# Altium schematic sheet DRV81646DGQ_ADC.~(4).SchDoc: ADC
size 431 x 279 mm; Date: Not shown in title block; ApprovedBy: Not shown in title block; CheckedBy: Not shown in title block; Author: Not shown in title block; CompanyName: Not shown in title block; DrawnBy: Mojtaba Afshar; Engineer: Not shown in title block; Organization: Not shown in title block; Address1: Not shown in title block; Address2: Not shown in title block; Address3: Not shown in title block; Address4: Not shown in title block; DocumentNumber: 2; Revision: Use project parameter SCH_Rev; SheetNumber: 4; SheetTotal: 5; PageSetup: Record=PageOptions¦CenterHorizontal=True¦CenterVertical=True¦PrintScale=1.00¦XCorrection=1.00¦YCorrection=1.00¦PrintKind=0¦BorderSize=5000000¦LeftOffset=0¦BottomOffset=0¦Orientation=2¦PaperLength=1000¦PaperWidth=1000¦Scale=100¦PaperSource=15¦PrintQuality=600¦MediaType=1¦DitherType=10¦PaperKind=Letter¦PrintScaleMode=1
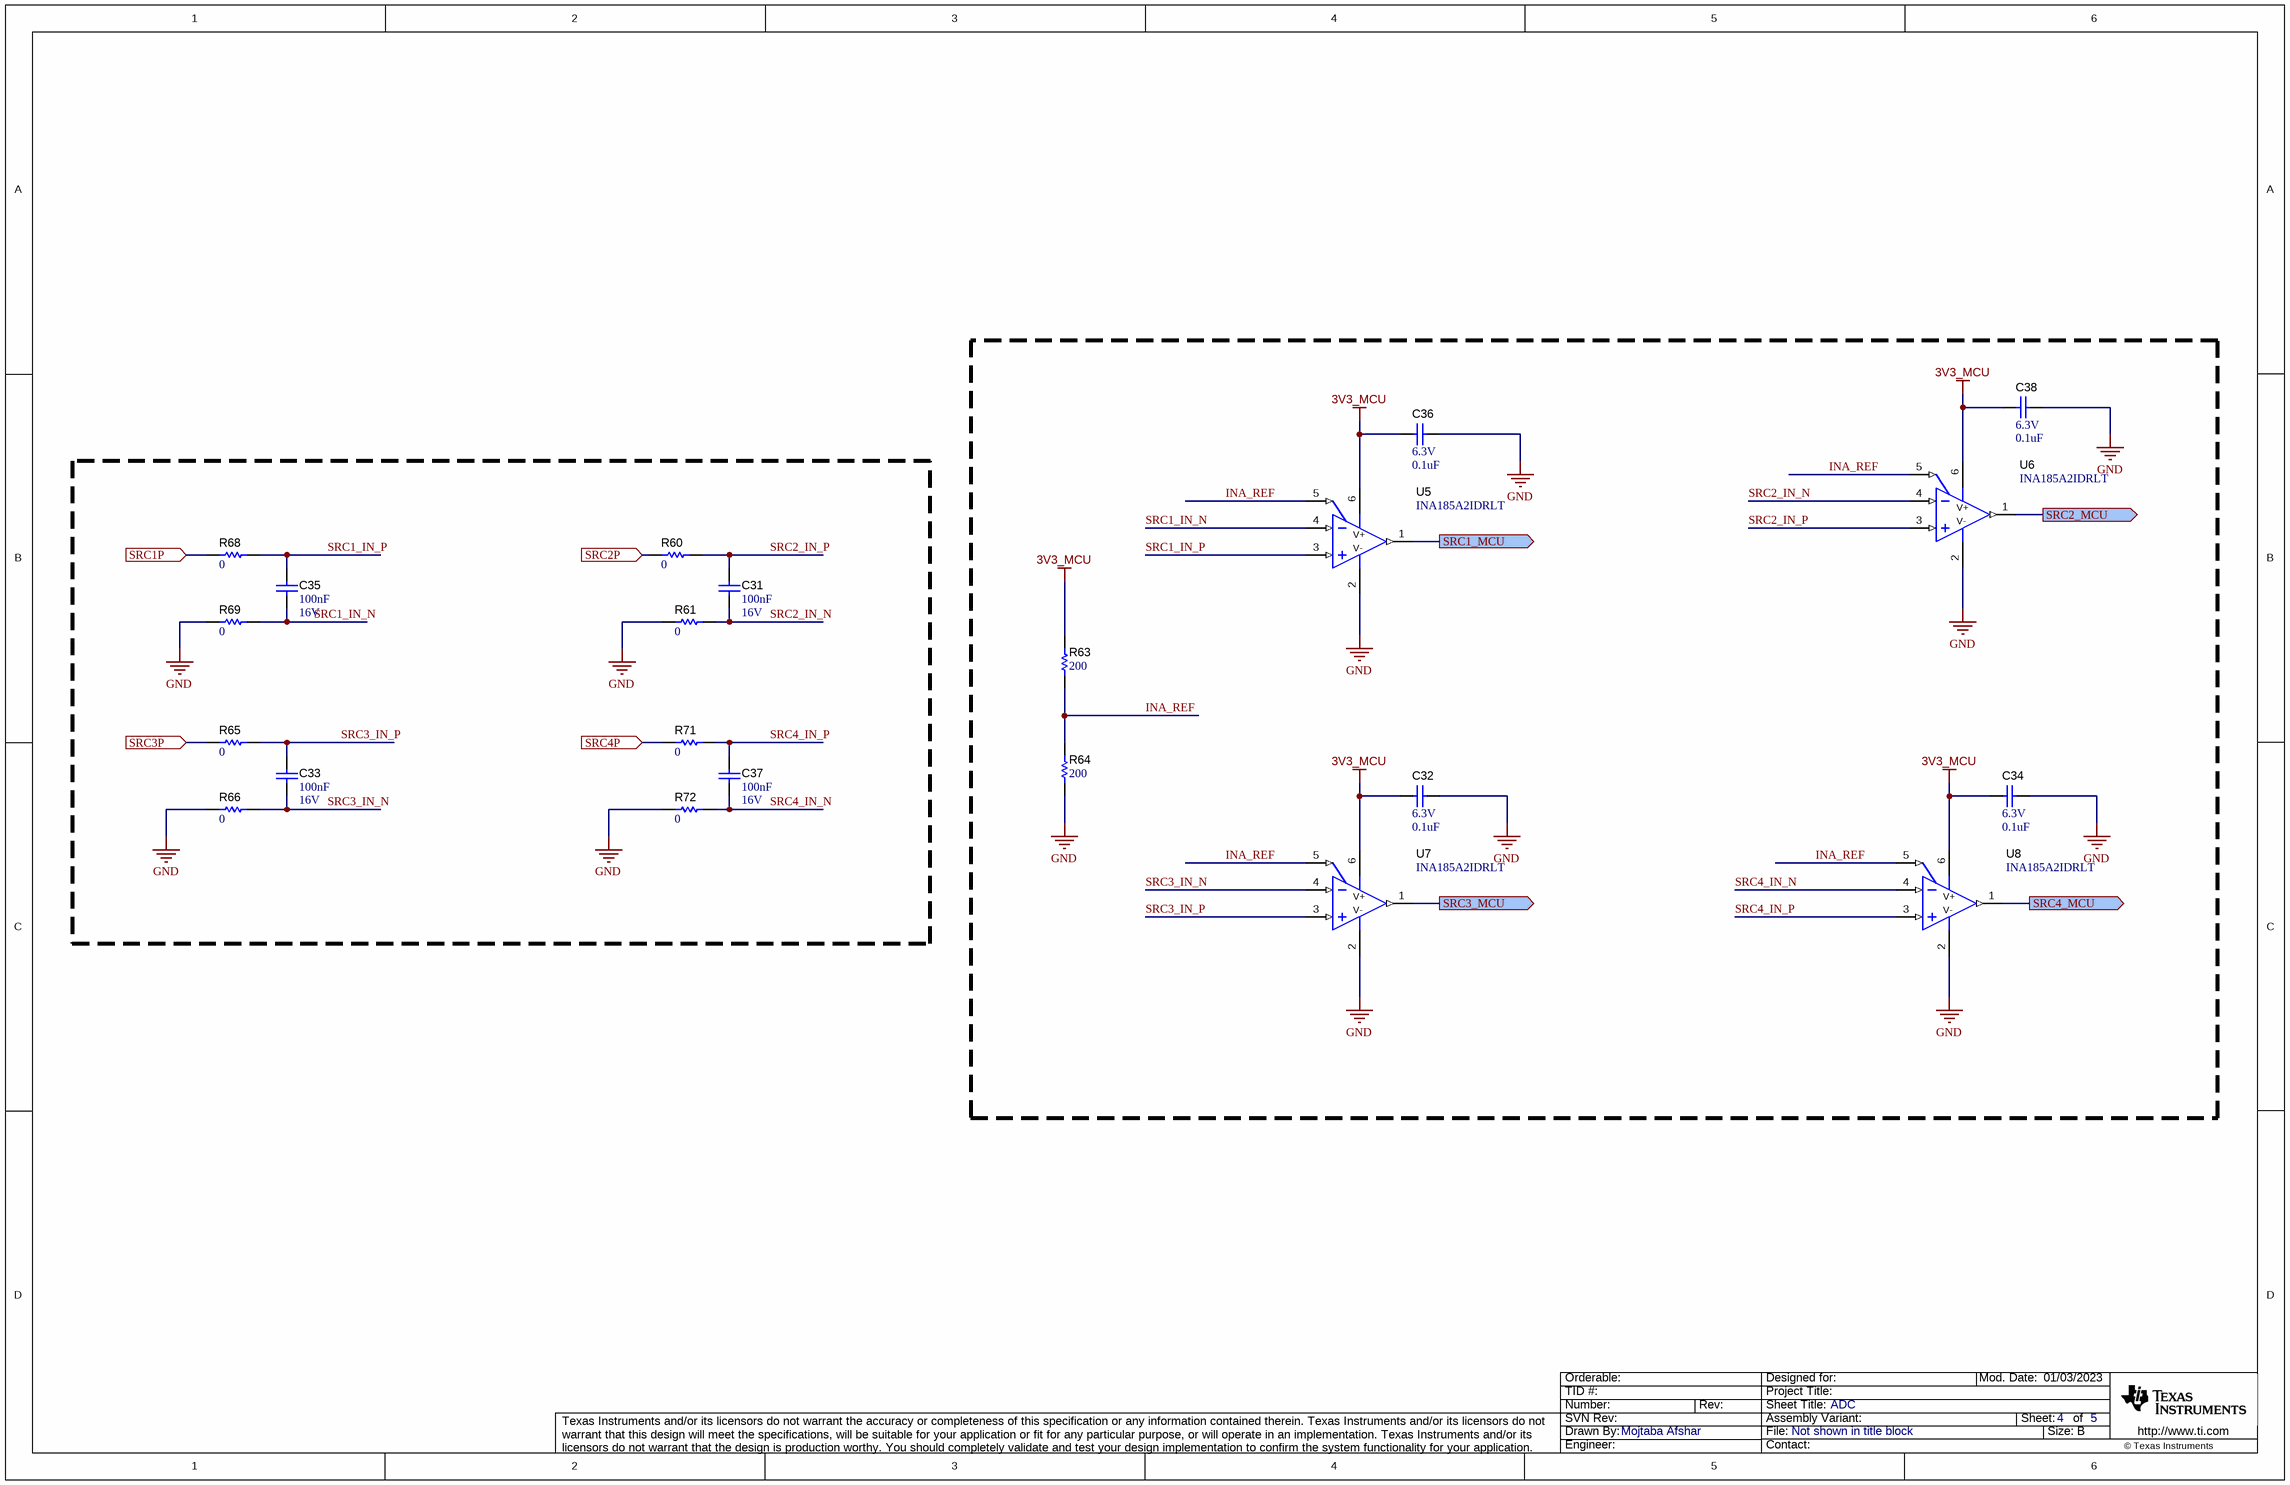
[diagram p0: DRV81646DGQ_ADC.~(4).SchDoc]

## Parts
C31  Cap_F: 100nF  VDC_V: 16V  [0603]  (hidden comment: 885012206046)
C32  VDC_V: 6.3V  ValueDisplayed: 0.1uF  [0402]  (hidden comment: 885012105001)
C33  Cap_F: 100nF  VDC_V: 16V  [0603]  (hidden comment: 885012206046)
C34  VDC_V: 6.3V  ValueDisplayed: 0.1uF  [0402]  (hidden comment: 885012105001)
C35  Cap_F: 100nF  VDC_V: 16V  [0603]  (hidden comment: 885012206046)
C36  VDC_V: 6.3V  ValueDisplayed: 0.1uF  [0402]  (hidden comment: 885012105001)
C37  Cap_F: 100nF  VDC_V: 16V  [0603]  (hidden comment: 885012206046)
C38  VDC_V: 6.3V  ValueDisplayed: 0.1uF  [0402]  (hidden comment: 885012105001)
R60  ValueDisplayed: 0  [0603]  (hidden comment: ERJ-3GEY0R00V)
R61  ValueDisplayed: 0  [0603]  (hidden comment: ERJ-3GEY0R00V)
R63  ValueDisplayed: 200  [0603]  (hidden comment: RC0603FR-07200RL)
R64  ValueDisplayed: 200  [0603]  (hidden comment: RC0603FR-07200RL)
R65  ValueDisplayed: 0  [0603]  (hidden comment: ERJ-3GEY0R00V)
R66  ValueDisplayed: 0  [0603]  (hidden comment: ERJ-3GEY0R00V)
R68  ValueDisplayed: 0  [0603]  (hidden comment: ERJ-3GEY0R00V)
R69  ValueDisplayed: 0  [0603]  (hidden comment: ERJ-3GEY0R00V)
R71  ValueDisplayed: 0  [0603]  (hidden comment: ERJ-3GEY0R00V)
R72  ValueDisplayed: 0  [0603]  (hidden comment: ERJ-3GEY0R00V)
U5  INA185A2IDRLT  [DRL0006A]
U6  INA185A2IDRLT  [DRL0006A]
U7  INA185A2IDRLT  [DRL0006A]
U8  INA185A2IDRLT  [DRL0006A]

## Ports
SRC1_MCU (out), SRC1P (in), SRC2_MCU (out), SRC2P (in), SRC3_MCU (out), SRC3P (in), SRC4_MCU (out), SRC4P (in)

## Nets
3V3_MCU: C32.2 C34.2 C36.2 C38.2 R63.2 U5.6(V+) U6.6(V+) U7.6(V+) U8.6(V+)
GND: C32.1 C34.1 C36.1 C38.1 R61.1 R64.1 R66.1 R69.1 R72.1 U5.2(V-) U6.2(V-) U7.2(V-) U8.2(V-)
INA_REF: R63.1 R64.2 U5.5(REF) U6.5(REF) U7.5(REF) U8.5(REF)
SRC1_IN_N: C35.2 R69.2 U5.4(IN-)
SRC1_IN_P: C35.1 R68.2 U5.3(IN+)
SRC1_MCU: U5.1(OUT) ; port SRC1_MCU
SRC1P: R68.1 ; port SRC1P
SRC2_IN_N: C31.2 R61.2 U6.4(IN-)
SRC2_IN_P: C31.1 R60.2 U6.3(IN+)
SRC2_MCU: U6.1(OUT) ; port SRC2_MCU
SRC2P: R60.1 ; port SRC2P
SRC3_IN_N: C33.2 R66.2 U7.4(IN-)
SRC3_IN_P: C33.1 R65.2 U7.3(IN+)
SRC3_MCU: U7.1(OUT) ; port SRC3_MCU
SRC3P: R65.1 ; port SRC3P
SRC4_IN_N: C37.2 R72.2 U8.4(IN-)
SRC4_IN_P: C37.1 R71.2 U8.3(IN+)
SRC4_MCU: U8.1(OUT) ; port SRC4_MCU
SRC4P: R71.1 ; port SRC4P

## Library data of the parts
C31 C33 C35 C37 = CMP-0006829-4: CAP, CERM, 0.1 uF, 16 V, +/- 10%, X7R, 0603; Manufacturer: Wurth Elektronik; TaMin_C: -55°C; Polarized: N; SizeAreaWB_mm2: 4.68; Value1: Unknown; U/M: EA; Value: 0.1uF; TaMax_C: 125°C; SizeZ_mm: 1; SizeX_mm: 1.6; SizeY_mm: 0.8; SizeArea_mm2: 1.28; AEC Category: Q200
C32 C34 C36 C38 = CMP-0006219-2: CAP, CERM, 0.1 uF, 6.3 V, +/- 20%, X5R, 0402; Manufacturer: Wurth Elektronik; TaMin_C: -55°C; Polarized: N; SizeAreaWB_mm2: 3; Value1: Unknown; U/M: EA; Value: 0.1uF; TaMax_C: 85°C; SizeZ_mm: 0.6; SizeX_mm: 1; SizeY_mm: 0.5; Cap_F: 100nF; AEC Category: Q200
R60 R61 R65 R66 R68 R69 R71 R72 = CMP-0025874-4: RES, 0, 5%, 0.1 W, AEC-Q200 Grade 0, 0603; Manufacturer: Panasonic; Power_W: 100mW; TempCo: 600 ppm/C; Value_Code: 0000; Value: 0; EIA_Code: E24; SizeX_mm: 1.6; SizeY_mm: 0.8; SizeZ_mm: 1; Value2: 0.1W; SizeArea_mm2: 1.28; AEC Qualified: Y; VDC_V: 50V; AEC Category: Q200; SizeAreaWB_mm2: 4.68
R63 R64 = CMP-0022902-5: RES, 200, 1%, 0.1 W, 0603; Manufacturer: Yageo; Power_W: 100mW; TempCo: 100 ppm/C; Value_Code: 200R; Value: 200; EIA_Code: E96; SizeX_mm: 1.6; SizeY_mm: 0.8; SizeZ_mm: 1; Value2: 0.1W; SizeArea_mm2: 1.28; AEC Qualified: N; VDC_V: 75V; AEC Category: Q200; SizeAreaWB_mm2: 4.68
U5-U8 = CMP-0085241-1: Bidirectional, Precision Low- and High-Side Voltage Output, Current-Sense Amplifier, DRL0006A (SOT-5X3-6); Alternate Manufacturer: Texas Instruments; Alternate PartNumber: INA185A2IDRLR; SizeZ_mm: 0.6; CompType: IC; SizeY_mm: 1.6; SizeAreaWB_mm2: 6.76; AEC Qualified: N; SizeArea_mm2: 2.56; AEC Category: Q200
